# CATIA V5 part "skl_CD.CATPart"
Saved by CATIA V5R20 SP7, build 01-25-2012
Part number: skl_CD
Publications: "Axe_CD_D", "AXE_CD_C", "CD", "Point C", "Point D", "Plan.1"
Bounding box of the stored display mesh (mm): x 0 to 10, y -2.039 to 38.15, z 59.286 to 75.132
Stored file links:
  U:\IAO-Thinkmotion\TRAVAIL A RENDRE\skl_CD.CATPart
  U:\IAO-Thinkmotion\TRAVAIL A RENDRE\skl_levier2bras.CATProduct
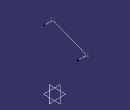
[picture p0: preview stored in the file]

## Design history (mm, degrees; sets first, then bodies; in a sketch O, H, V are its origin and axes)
Set1
  DatumPoint1 "Point C": linked copy from another document
  DatumPoint2 "Point D": linked copy from another document
  Plane1: linked copy from another document
Set2
  Line1 "CD": type PtPt, FirstPoint DatumPoint1, SecondPoint DatumPoint2
  Line2 "AXE_CD_C": type Normal, RefPoint DatumPoint1, RefSkin Plane1, Start 0, End 10
  Line3 "Axe_CD_D": type Normal, RefPoint DatumPoint2, RefSkin Plane1, Start 0, End 10
Body1 (main body)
